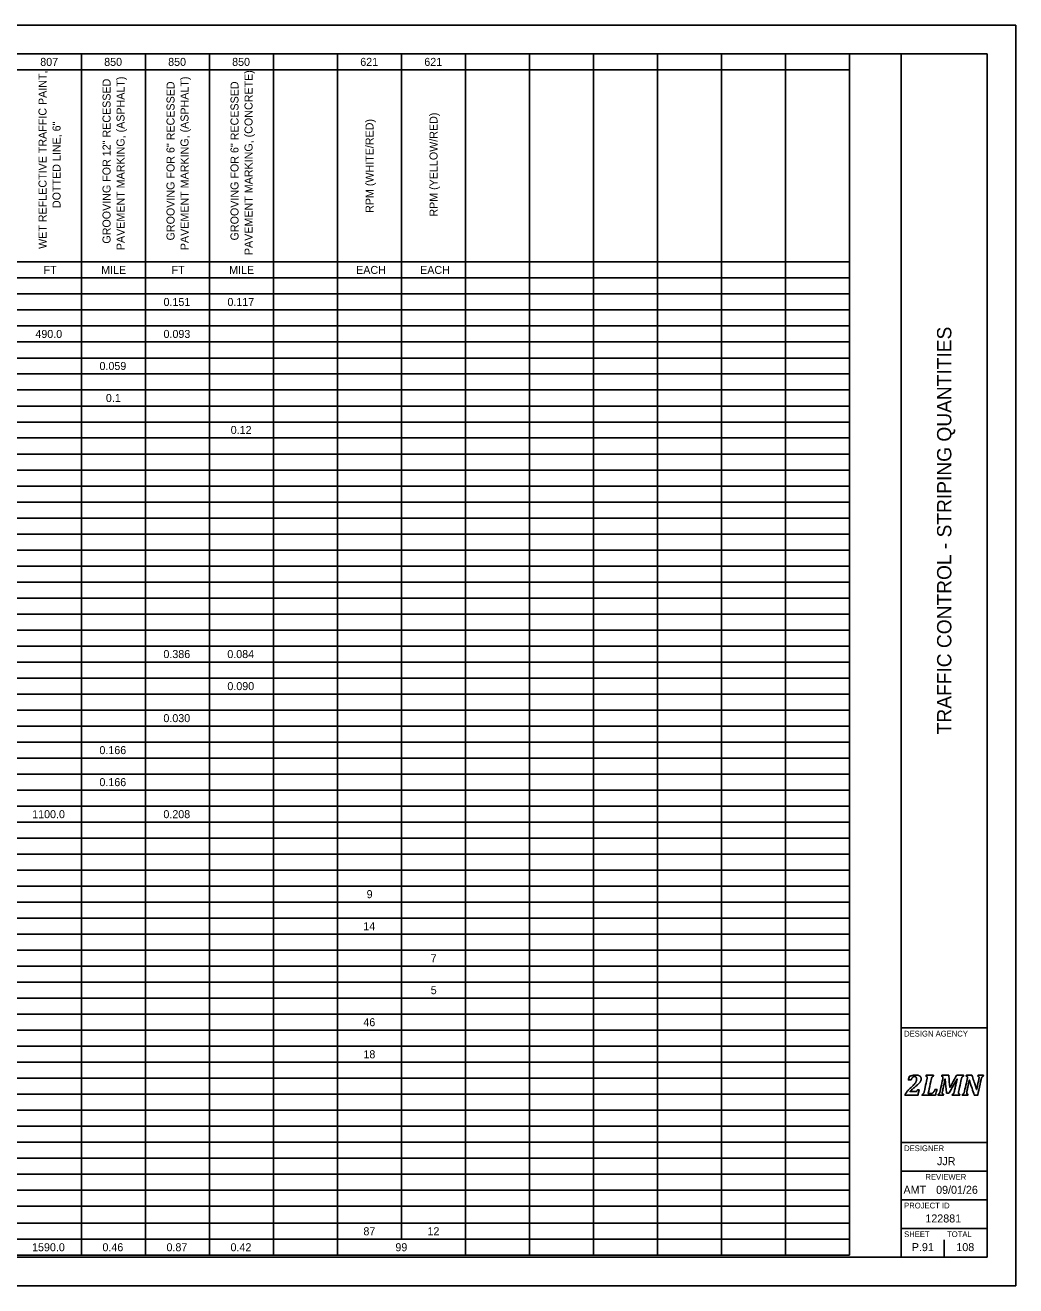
# Model space of a CAD drawing. Extents: x 0 to 34, y 0 to 22.
# Drawn here: x 16.7 to 34, y 0 to 22 of the extents above; entities that cross this region are included whole.
import ezdxf

# ---------------------------------------------------------------- set-up
doc = ezdxf.new("R2010")
doc.units = 0
for name, color, linetype in [('SH_Border', 7, 'Continuous'), ('SH_Cut_Line', 7, 'Continuous'), ('SH_Data', 7, 'Continuous'), ('SH_Text', 7, 'Continuous')]:
    doc.layers.add(name, color=color, linetype=linetype)

msp = doc.modelspace()

# ---------------------------------------------------------------- linework, layer by layer
at = {"layer": 'SH_Border'}
for p, q in [((32, 0.5), (32, 21.5)), ((32, 4.5), (33.5, 4.5)), ((32, 2.5), (33.5, 2.5)), ((32, 2), (33.5, 2)), ((32, 1.5), (33.5, 1.5)), ((32, 1), (33.5, 1))]:
    msp.add_line(p, q, dxfattribs=at)
msp.add_lwpolyline([(1.5, 21.5), (33.5, 21.5), (33.5, 0.5), (1.5, 0.5)], close=True, dxfattribs=at)
at = {"layer": 'SH_Cut_Line'}
msp.add_lwpolyline([(0, 0), (34, 0), (34, 22), (0, 22)], close=True, dxfattribs=at)
at = {"layer": 'SH_Data'}
for p, q in [((32.75, 3.5), (32.75, 3.5)), ((32.375, 0.675), (32.375, 0.675)), ((32.75, 0.5), (32.75, 0.8))]:
    msp.add_line(p, q, dxfattribs=at)
for points in [[(32.237, 3.388), (32.246, 3.388), (32.253, 3.389), (32.258, 3.39), (32.263, 3.392), (32.267, 3.394), (32.27, 3.397), (32.273, 3.401), (32.277, 3.408), (32.281, 3.417), (32.281, 3.417), (32.312, 3.417), (32.312, 3.417), (32.312, 3.417), (32.29, 3.326), (32.29, 3.326), (32.29, 3.326), (32.066, 3.326), (32.066, 3.326), (32.066, 3.326), (32.069, 3.343), (32.069, 3.343), (32.078, 3.358), (32.091, 3.375), (32.106, 3.394), (32.122, 3.412), (32.144, 3.435), (32.172, 3.462), (32.197, 3.486), (32.217, 3.506), (32.23, 3.521), (32.243, 3.537), (32.253, 3.551), (32.259, 3.566), (32.266, 3.58), (32.269, 3.595), (32.269, 3.61), (32.269, 3.622), (32.266, 3.632), (32.26, 3.64), (32.253, 3.647), (32.245, 3.65), (32.234, 3.65), (32.22, 3.65), (32.208, 3.646), (32.198, 3.636), (32.188, 3.627), (32.18, 3.613), (32.172, 3.593), (32.172, 3.593), (32.126, 3.593), (32.126, 3.593), (32.126, 3.593), (32.14, 3.654), (32.14, 3.654), (32.166, 3.663), (32.188, 3.669), (32.205, 3.673), (32.223, 3.676), (32.24, 3.678), (32.258, 3.678), (32.278, 3.678), (32.295, 3.675), (32.309, 3.669), (32.322, 3.664), (32.332, 3.656), (32.339, 3.646), (32.345, 3.637), (32.348, 3.626), (32.348, 3.613), (32.348, 3.602), (32.346, 3.591), (32.342, 3.581), (32.339, 3.571), (32.333, 3.56), (32.324, 3.549), (32.315, 3.539), (32.304, 3.526), (32.289, 3.513), (32.275, 3.499), (32.254, 3.482), (32.228, 3.46), (32.216, 3.45), (32.202, 3.438), (32.188, 3.425), (32.174, 3.412), (32.162, 3.4), (32.154, 3.391), (32.154, 3.391), (32.153, 3.388), (32.153, 3.388), (32.153, 3.388), (32.237, 3.388), (32.237, 3.388)], [(32.237, 3.388), (32.237, 3.388), (32.153, 3.388), (32.153, 3.388), (32.153, 3.388), (32.154, 3.391), (32.154, 3.391), (32.162, 3.4), (32.174, 3.412), (32.188, 3.425), (32.202, 3.438), (32.216, 3.45), (32.228, 3.46), (32.254, 3.482), (32.275, 3.499), (32.289, 3.513), (32.304, 3.526), (32.315, 3.539), (32.324, 3.549), (32.333, 3.56), (32.339, 3.571), (32.342, 3.581), (32.346, 3.591), (32.348, 3.602), (32.348, 3.613), (32.348, 3.626), (32.345, 3.637), (32.339, 3.646), (32.332, 3.656), (32.322, 3.664), (32.309, 3.669), (32.295, 3.675), (32.278, 3.678), (32.258, 3.678), (32.24, 3.678), (32.223, 3.676), (32.205, 3.673), (32.188, 3.669), (32.166, 3.663), (32.14, 3.654), (32.14, 3.654), (32.126, 3.593), (32.126, 3.593), (32.126, 3.593), (32.172, 3.593), (32.172, 3.593), (32.18, 3.613), (32.188, 3.627), (32.198, 3.636), (32.208, 3.646), (32.22, 3.65), (32.234, 3.65), (32.245, 3.65), (32.253, 3.647), (32.26, 3.64), (32.266, 3.632), (32.269, 3.622), (32.269, 3.61), (32.269, 3.595), (32.266, 3.58), (32.259, 3.566), (32.253, 3.551), (32.243, 3.537), (32.23, 3.521), (32.217, 3.506), (32.197, 3.486), (32.172, 3.462), (32.144, 3.435), (32.122, 3.412), (32.106, 3.394), (32.091, 3.375), (32.078, 3.358), (32.069, 3.343), (32.069, 3.343), (32.066, 3.326), (32.066, 3.326), (32.066, 3.326), (32.29, 3.326), (32.29, 3.326), (32.29, 3.326), (32.312, 3.417), (32.312, 3.417), (32.312, 3.417), (32.281, 3.417), (32.281, 3.417), (32.277, 3.408), (32.273, 3.401), (32.27, 3.397), (32.267, 3.394), (32.263, 3.392), (32.258, 3.39), (32.253, 3.389), (32.246, 3.388), (32.237, 3.388)], [(32.518, 3.356), (32.527, 3.356), (32.533, 3.357), (32.538, 3.358), (32.542, 3.36), (32.546, 3.362), (32.55, 3.365), (32.554, 3.368), (32.558, 3.372), (32.562, 3.377), (32.567, 3.382), (32.571, 3.388), (32.576, 3.397), (32.58, 3.405), (32.585, 3.415), (32.589, 3.427), (32.589, 3.427), (32.624, 3.427), (32.624, 3.427), (32.624, 3.427), (32.598, 3.326), (32.598, 3.326), (32.598, 3.326), (32.365, 3.326), (32.365, 3.326), (32.365, 3.326), (32.369, 3.343), (32.369, 3.343), (32.376, 3.345), (32.381, 3.348), (32.385, 3.351), (32.389, 3.355), (32.392, 3.36), (32.395, 3.366), (32.398, 3.373), (32.4, 3.382), (32.403, 3.395), (32.403, 3.395), (32.449, 3.605), (32.449, 3.605), (32.452, 3.615), (32.453, 3.625), (32.453, 3.635), (32.453, 3.642), (32.451, 3.647), (32.448, 3.651), (32.444, 3.654), (32.439, 3.656), (32.432, 3.657), (32.432, 3.657), (32.435, 3.674), (32.435, 3.674), (32.435, 3.674), (32.563, 3.674), (32.563, 3.674), (32.563, 3.674), (32.559, 3.657), (32.559, 3.657), (32.552, 3.655), (32.547, 3.652), (32.543, 3.649), (32.539, 3.645), (32.536, 3.64), (32.533, 3.634), (32.531, 3.627), (32.528, 3.618), (32.525, 3.605), (32.525, 3.605), (32.47, 3.356), (32.47, 3.356), (32.47, 3.356), (32.518, 3.356), (32.518, 3.356)], [(32.518, 3.356), (32.518, 3.356), (32.47, 3.356), (32.47, 3.356), (32.47, 3.356), (32.525, 3.605), (32.525, 3.605), (32.528, 3.618), (32.531, 3.627), (32.533, 3.634), (32.536, 3.64), (32.539, 3.645), (32.543, 3.649), (32.547, 3.652), (32.552, 3.655), (32.559, 3.657), (32.559, 3.657), (32.563, 3.674), (32.563, 3.674), (32.563, 3.674), (32.435, 3.674), (32.435, 3.674), (32.435, 3.674), (32.432, 3.657), (32.432, 3.657), (32.439, 3.656), (32.444, 3.654), (32.448, 3.651), (32.451, 3.647), (32.453, 3.642), (32.453, 3.635), (32.453, 3.625), (32.452, 3.615), (32.449, 3.605), (32.449, 3.605), (32.403, 3.395), (32.403, 3.395), (32.4, 3.382), (32.398, 3.373), (32.395, 3.366), (32.392, 3.36), (32.389, 3.355), (32.385, 3.351), (32.381, 3.348), (32.376, 3.345), (32.369, 3.343), (32.369, 3.343), (32.365, 3.326), (32.365, 3.326), (32.365, 3.326), (32.598, 3.326), (32.598, 3.326), (32.598, 3.326), (32.624, 3.427), (32.624, 3.427), (32.624, 3.427), (32.589, 3.427), (32.589, 3.427), (32.585, 3.415), (32.58, 3.405), (32.576, 3.397), (32.571, 3.388), (32.567, 3.382), (32.562, 3.377), (32.558, 3.372), (32.554, 3.368), (32.55, 3.365), (32.546, 3.362), (32.542, 3.36), (32.538, 3.358), (32.533, 3.357), (32.527, 3.356), (32.518, 3.356)], [(32.829, 3.674), (32.829, 3.674), (32.849, 3.461), (32.849, 3.461), (32.849, 3.461), (32.969, 3.674), (32.969, 3.674), (32.969, 3.674), (33.087, 3.674), (33.087, 3.674), (33.087, 3.674), (33.084, 3.657), (33.084, 3.657), (33.077, 3.655), (33.071, 3.652), (33.067, 3.649), (33.064, 3.645), (33.06, 3.64), (33.058, 3.634), (33.055, 3.627), (33.052, 3.618), (33.05, 3.605), (33.05, 3.605), (33.003, 3.395), (33.003, 3.395), (33.002, 3.39), (33.002, 3.387), (33.001, 3.384), (33.001, 3.382), (33.001, 3.379), (33, 3.376), (33, 3.373), (33, 3.369), (33, 3.365), (33, 3.358), (33.002, 3.353), (33.005, 3.349), (33.008, 3.346), (33.014, 3.344), (33.021, 3.343), (33.021, 3.343), (33.018, 3.326), (33.018, 3.326), (33.018, 3.326), (32.89, 3.326), (32.89, 3.326), (32.89, 3.326), (32.893, 3.343), (32.893, 3.343), (32.9, 3.345), (32.906, 3.348), (32.91, 3.351), (32.914, 3.355), (32.917, 3.36), (32.919, 3.366), (32.922, 3.373), (32.925, 3.382), (32.928, 3.395), (32.928, 3.395), (32.951, 3.502), (32.951, 3.502), (32.954, 3.513), (32.957, 3.529), (32.962, 3.548), (32.967, 3.568), (32.972, 3.588), (32.978, 3.609), (32.978, 3.609), (32.973, 3.609), (32.973, 3.609), (32.965, 3.594), (32.957, 3.579), (32.948, 3.563), (32.948, 3.563), (32.833, 3.364), (32.833, 3.364), (32.833, 3.364), (32.792, 3.364), (32.792, 3.364), (32.792, 3.364), (32.775, 3.518), (32.775, 3.518), (32.773, 3.537), (32.772, 3.554), (32.77, 3.569), (32.769, 3.583), (32.768, 3.597), (32.768, 3.611), (32.768, 3.611), (32.764, 3.611), (32.764, 3.611), (32.761, 3.596), (32.758, 3.578), (32.755, 3.558), (32.751, 3.538), (32.747, 3.521), (32.744, 3.507), (32.744, 3.507), (32.72, 3.395), (32.72, 3.395), (32.719, 3.39), (32.718, 3.387), (32.718, 3.384), (32.717, 3.382), (32.717, 3.379), (32.717, 3.376), (32.717, 3.373), (32.716, 3.369), (32.716, 3.365), (32.716, 3.358), (32.718, 3.353), (32.721, 3.349), (32.725, 3.346), (32.73, 3.344), (32.738, 3.343), (32.738, 3.343), (32.734, 3.326), (32.734, 3.326), (32.734, 3.326), (32.641, 3.326), (32.641, 3.326), (32.641, 3.326), (32.644, 3.343), (32.644, 3.343), (32.651, 3.345), (32.657, 3.348), (32.661, 3.351), (32.665, 3.355), (32.668, 3.36), (32.67, 3.366), (32.673, 3.373), (32.676, 3.382), (32.679, 3.395), (32.679, 3.395), (32.725, 3.605), (32.725, 3.605), (32.727, 3.615), (32.728, 3.625), (32.728, 3.635), (32.728, 3.642), (32.727, 3.647), (32.723, 3.651), (32.72, 3.654), (32.715, 3.656), (32.707, 3.657), (32.707, 3.657), (32.711, 3.674), (32.711, 3.674), (32.711, 3.674), (32.829, 3.674), (32.829, 3.674)], [(32.829, 3.674), (32.829, 3.674), (32.711, 3.674), (32.711, 3.674), (32.711, 3.674), (32.707, 3.657), (32.707, 3.657), (32.715, 3.656), (32.72, 3.654), (32.723, 3.651), (32.727, 3.647), (32.728, 3.642), (32.728, 3.635), (32.728, 3.625), (32.727, 3.615), (32.725, 3.605), (32.725, 3.605), (32.679, 3.395), (32.679, 3.395), (32.676, 3.382), (32.673, 3.373), (32.67, 3.366), (32.668, 3.36), (32.665, 3.355), (32.661, 3.351), (32.657, 3.348), (32.651, 3.345), (32.644, 3.343), (32.644, 3.343), (32.641, 3.326), (32.641, 3.326), (32.641, 3.326), (32.734, 3.326), (32.734, 3.326), (32.734, 3.326), (32.738, 3.343), (32.738, 3.343), (32.73, 3.344), (32.725, 3.346), (32.721, 3.349), (32.718, 3.353), (32.716, 3.358), (32.716, 3.365), (32.716, 3.369), (32.717, 3.373), (32.717, 3.376), (32.717, 3.379), (32.717, 3.382), (32.718, 3.384), (32.718, 3.387), (32.719, 3.39), (32.72, 3.395), (32.72, 3.395), (32.744, 3.507), (32.744, 3.507), (32.747, 3.521), (32.751, 3.538), (32.755, 3.558), (32.758, 3.578), (32.761, 3.596), (32.764, 3.611), (32.764, 3.611), (32.768, 3.611), (32.768, 3.611), (32.768, 3.597), (32.769, 3.583), (32.77, 3.569), (32.772, 3.554), (32.773, 3.537), (32.775, 3.518), (32.775, 3.518), (32.792, 3.364), (32.792, 3.364), (32.792, 3.364), (32.833, 3.364), (32.833, 3.364), (32.833, 3.364), (32.948, 3.563), (32.948, 3.563), (32.957, 3.579), (32.965, 3.594), (32.973, 3.609), (32.973, 3.609), (32.978, 3.609), (32.978, 3.609), (32.972, 3.588), (32.967, 3.568), (32.962, 3.548), (32.957, 3.529), (32.954, 3.513), (32.951, 3.502), (32.951, 3.502), (32.928, 3.395), (32.928, 3.395), (32.925, 3.382), (32.922, 3.373), (32.919, 3.366), (32.917, 3.36), (32.914, 3.355), (32.91, 3.351), (32.906, 3.348), (32.9, 3.345), (32.893, 3.343), (32.893, 3.343), (32.89, 3.326), (32.89, 3.326), (32.89, 3.326), (33.018, 3.326), (33.018, 3.326), (33.018, 3.326), (33.021, 3.343), (33.021, 3.343), (33.014, 3.344), (33.008, 3.346), (33.005, 3.349), (33.002, 3.353), (33, 3.358), (33, 3.365), (33, 3.369), (33, 3.373), (33, 3.376), (33.001, 3.379), (33.001, 3.382), (33.001, 3.384), (33.002, 3.387), (33.002, 3.39), (33.003, 3.395), (33.003, 3.395), (33.05, 3.605), (33.05, 3.605), (33.052, 3.618), (33.055, 3.627), (33.058, 3.634), (33.06, 3.64), (33.064, 3.645), (33.067, 3.649), (33.071, 3.652), (33.077, 3.655), (33.084, 3.657), (33.084, 3.657), (33.087, 3.674), (33.087, 3.674), (33.087, 3.674), (32.969, 3.674), (32.969, 3.674), (32.969, 3.674), (32.849, 3.461), (32.849, 3.461), (32.849, 3.461), (32.829, 3.674), (32.829, 3.674)], [(33.137, 3.674), (33.137, 3.674), (33.234, 3.674), (33.234, 3.674), (33.234, 3.674), (33.283, 3.53), (33.283, 3.53), (33.296, 3.49), (33.307, 3.456), (33.315, 3.426), (33.315, 3.426), (33.318, 3.426), (33.318, 3.426), (33.323, 3.455), (33.329, 3.488), (33.337, 3.523), (33.337, 3.523), (33.355, 3.605), (33.355, 3.605), (33.357, 3.615), (33.358, 3.625), (33.358, 3.635), (33.358, 3.642), (33.357, 3.647), (33.353, 3.651), (33.35, 3.654), (33.345, 3.656), (33.337, 3.657), (33.337, 3.657), (33.341, 3.674), (33.341, 3.674), (33.341, 3.674), (33.434, 3.674), (33.434, 3.674), (33.434, 3.674), (33.431, 3.657), (33.431, 3.657), (33.424, 3.655), (33.418, 3.652), (33.414, 3.649), (33.41, 3.645), (33.407, 3.64), (33.405, 3.634), (33.402, 3.627), (33.399, 3.618), (33.396, 3.605), (33.396, 3.605), (33.335, 3.326), (33.335, 3.326), (33.335, 3.326), (33.277, 3.326), (33.277, 3.326), (33.277, 3.326), (33.216, 3.504), (33.216, 3.504), (33.211, 3.518), (33.207, 3.531), (33.204, 3.543), (33.2, 3.556), (33.195, 3.571), (33.19, 3.59), (33.19, 3.59), (33.186, 3.59), (33.186, 3.59), (33.185, 3.579), (33.182, 3.563), (33.179, 3.543), (33.175, 3.523), (33.17, 3.501), (33.165, 3.478), (33.165, 3.478), (33.147, 3.395), (33.147, 3.395), (33.146, 3.39), (33.145, 3.387), (33.145, 3.384), (33.144, 3.382), (33.144, 3.379), (33.144, 3.376), (33.143, 3.373), (33.143, 3.369), (33.143, 3.365), (33.143, 3.358), (33.145, 3.353), (33.148, 3.349), (33.152, 3.346), (33.157, 3.344), (33.164, 3.343), (33.164, 3.343), (33.161, 3.326), (33.161, 3.326), (33.161, 3.326), (33.067, 3.326), (33.067, 3.326), (33.067, 3.326), (33.071, 3.343), (33.071, 3.343), (33.078, 3.345), (33.083, 3.348), (33.087, 3.351), (33.091, 3.355), (33.094, 3.36), (33.097, 3.366), (33.1, 3.373), (33.102, 3.382), (33.105, 3.395), (33.105, 3.395), (33.151, 3.605), (33.151, 3.605), (33.154, 3.615), (33.155, 3.625), (33.155, 3.635), (33.155, 3.642), (33.153, 3.647), (33.15, 3.651), (33.146, 3.654), (33.141, 3.656), (33.134, 3.657), (33.134, 3.657), (33.137, 3.674), (33.137, 3.674)], [(33.137, 3.674), (33.137, 3.674), (33.134, 3.657), (33.134, 3.657), (33.141, 3.656), (33.146, 3.654), (33.15, 3.651), (33.153, 3.647), (33.155, 3.642), (33.155, 3.635), (33.155, 3.625), (33.154, 3.615), (33.151, 3.605), (33.151, 3.605), (33.105, 3.395), (33.105, 3.395), (33.102, 3.382), (33.1, 3.373), (33.097, 3.366), (33.094, 3.36), (33.091, 3.355), (33.087, 3.351), (33.083, 3.348), (33.078, 3.345), (33.071, 3.343), (33.071, 3.343), (33.067, 3.326), (33.067, 3.326), (33.067, 3.326), (33.161, 3.326), (33.161, 3.326), (33.161, 3.326), (33.164, 3.343), (33.164, 3.343), (33.157, 3.344), (33.152, 3.346), (33.148, 3.349), (33.145, 3.353), (33.143, 3.358), (33.143, 3.365), (33.143, 3.369), (33.143, 3.373), (33.144, 3.376), (33.144, 3.379), (33.144, 3.382), (33.145, 3.384), (33.145, 3.387), (33.146, 3.39), (33.147, 3.395), (33.147, 3.395), (33.165, 3.478), (33.165, 3.478), (33.17, 3.501), (33.175, 3.523), (33.179, 3.543), (33.182, 3.563), (33.185, 3.579), (33.186, 3.59), (33.186, 3.59), (33.19, 3.59), (33.19, 3.59), (33.195, 3.571), (33.2, 3.556), (33.204, 3.543), (33.207, 3.531), (33.211, 3.518), (33.216, 3.504), (33.216, 3.504), (33.277, 3.326), (33.277, 3.326), (33.277, 3.326), (33.335, 3.326), (33.335, 3.326), (33.335, 3.326), (33.396, 3.605), (33.396, 3.605), (33.399, 3.618), (33.402, 3.627), (33.405, 3.634), (33.407, 3.64), (33.41, 3.645), (33.414, 3.649), (33.418, 3.652), (33.424, 3.655), (33.431, 3.657), (33.431, 3.657), (33.434, 3.674), (33.434, 3.674), (33.434, 3.674), (33.341, 3.674), (33.341, 3.674), (33.341, 3.674), (33.337, 3.657), (33.337, 3.657), (33.345, 3.656), (33.35, 3.654), (33.353, 3.651), (33.357, 3.647), (33.358, 3.642), (33.358, 3.635), (33.358, 3.625), (33.357, 3.615), (33.355, 3.605), (33.355, 3.605), (33.337, 3.523), (33.337, 3.523), (33.329, 3.488), (33.323, 3.455), (33.318, 3.426), (33.318, 3.426), (33.315, 3.426), (33.315, 3.426), (33.307, 3.456), (33.296, 3.49), (33.283, 3.53), (33.283, 3.53), (33.234, 3.674), (33.234, 3.674), (33.234, 3.674), (33.137, 3.674), (33.137, 3.674)]]:
    msp.add_open_spline(points, degree=3, dxfattribs=at)
at = {"layer": 'SH_Text'}
for p, q in [((1.536, 21.5), (31.097, 21.5)), ((17.688, 21.5), (17.688, 0.533)), ((18.806, 21.5), (18.806, 0.533)), ((19.923, 21.5), (19.923, 0.533)), ((21.041, 21.5), (21.041, 0.533)), ((22.158, 21.5), (22.158, 0.533)), ((23.275, 21.5), (23.275, 0.812)), ((24.393, 21.5), (24.393, 0.533)), ((25.51, 21.5), (25.51, 0.533)), ((26.627, 21.5), (26.627, 0.533)), ((27.745, 21.5), (27.745, 0.533)), ((28.862, 21.5), (28.862, 0.533)), ((29.979, 21.5), (29.979, 0.533)), ((31.097, 21.5), (31.097, 0.533)), ((8.749, 21.221), (31.097, 21.221)), ((8.749, 17.869), (31.097, 17.869)), ((1.536, 17.589), (31.097, 17.589)), ((1.536, 17.31), (31.097, 17.31)), ((1.536, 17.031), (31.097, 17.031)), ((1.536, 16.751), (31.097, 16.751)), ((1.536, 16.472), (31.097, 16.472)), ((1.536, 16.192), (31.097, 16.192)), ((1.536, 15.913), (31.097, 15.913)), ((1.536, 15.634), (31.097, 15.634)), ((1.536, 15.354), (31.097, 15.354)), ((1.536, 15.075), (31.097, 15.075)), ((1.536, 14.796), (31.097, 14.796)), ((1.536, 14.516), (31.097, 14.516)), ((1.536, 14.237), (31.097, 14.237)), ((1.536, 13.958), (31.097, 13.958)), ((1.536, 13.678), (31.097, 13.678)), ((1.536, 13.399), (31.097, 13.399)), ((1.536, 13.12), (31.097, 13.12)), ((1.536, 12.84), (31.097, 12.84)), ((1.536, 12.561), (31.097, 12.561)), ((1.536, 12.282), (31.097, 12.282)), ((1.536, 12.002), (31.097, 12.002)), ((1.536, 11.723), (31.097, 11.723)), ((1.536, 11.444), (31.097, 11.444)), ((1.536, 11.164), (31.097, 11.164)), ((1.536, 10.885), (31.097, 10.885)), ((1.536, 10.606), (31.097, 10.606)), ((1.536, 10.326), (31.097, 10.326)), ((1.536, 10.047), (31.097, 10.047)), ((1.536, 9.768), (31.097, 9.768)), ((1.536, 9.488), (31.097, 9.488)), ((1.536, 9.209), (31.097, 9.209)), ((1.536, 8.93), (31.097, 8.93)), ((1.536, 8.65), (31.097, 8.65)), ((1.536, 8.371), (31.097, 8.371)), ((1.536, 8.092), (31.097, 8.092)), ((1.536, 7.812), (31.097, 7.812)), ((1.536, 7.533), (31.097, 7.533)), ((1.536, 7.254), (31.097, 7.254)), ((1.536, 6.974), (31.097, 6.974)), ((1.536, 6.695), (31.097, 6.695)), ((1.536, 6.415), (31.097, 6.415)), ((1.536, 6.136), (31.097, 6.136)), ((1.536, 5.857), (31.097, 5.857)), ((1.536, 5.577), (31.097, 5.577)), ((1.536, 5.298), (31.097, 5.298)), ((1.536, 5.019), (31.097, 5.019)), ((1.536, 4.739), (31.097, 4.739)), ((1.536, 4.46), (31.097, 4.46)), ((1.536, 4.181), (31.097, 4.181)), ((1.536, 3.901), (31.097, 3.901)), ((1.536, 3.622), (31.097, 3.622)), ((1.536, 3.343), (31.097, 3.343)), ((1.536, 3.063), (31.097, 3.063)), ((1.536, 2.784), (31.097, 2.784)), ((1.536, 2.505), (31.097, 2.505)), ((1.536, 2.225), (31.097, 2.225)), ((1.536, 1.946), (31.097, 1.946)), ((1.536, 1.667), (31.097, 1.667)), ((1.536, 1.387), (31.097, 1.387)), ((1.536, 1.092), (22.158, 1.092)), ((22.158, 1.092), (24.393, 1.092)), ((24.393, 1.092), (31.097, 1.092)), ((1.536, 0.812), (31.097, 0.812)), ((1.536, 0.533), (31.097, 0.533))]:
    msp.add_line(p, q, dxfattribs=at)

# ---------------------------------------------------------------- texts
at = {"layer": 'SH_Data'}
msp.add_text('TRAFFIC CONTROL - STRIPING QUANTITIES', height=0.25, rotation=90, dxfattribs=at).set_placement((32.875, 9.625))
for s, height, p in [('DESIGN AGENCY', 0.1, (32.05, 4.35)), ('DESIGNER', 0.1, (32.05, 2.35)), ('JJR', 0.14, (32.624, 2.105)), ('REVIEWER', 0.1, (32.422, 1.85)), ('AMT', 0.14, (32.039, 1.605)), ('09/01/26', 0.14, (32.609, 1.605)), ('PROJECT ID', 0.1, (32.05, 1.35)), ('122881', 0.14, (32.421, 1.105)), ('SHEET', 0.1, (32.05, 0.85)), ('TOTAL', 0.1, (32.8, 0.85)), ('P.91', 0.14, (32.184, 0.605)), ('108', 0.14, (32.962, 0.605))]:
    msp.add_text(s, height=height, dxfattribs=at).set_placement(p)
at = {"layer": 'SH_Text'}
for s, height, p in [('807', 0.1397, (16.968, 21.29)), ('850', 0.1397, (18.084, 21.29)), ('850', 0.1397, (19.201, 21.29)), ('850', 0.1397, (20.318, 21.29)), ('621', 0.1397, (22.555, 21.29)), ('621', 0.1397, (23.673, 21.29)), ('FT', 0.1397, (17.026, 17.659)), ('MILE', 0.1397, (18.031, 17.659)), ('FT', 0.1397, (19.261, 17.659)), ('MILE', 0.1397, (20.266, 17.659)), ('EACH', 0.1397, (22.483, 17.659)), ('EACH', 0.1397, (23.6, 17.659)), ('0.151', 0.1397, (19.12, 17.1)), ('0.117', 0.1397, (20.236, 17.1)), ('490.0', 0.1397, (16.883, 16.542)), ('0.093', 0.1397, (19.12, 16.542)), ('0.059', 0.1397, (18.002, 15.983)), ('0.1', 0.1397, (18.114, 15.424)), ('0.12', 0.1397, (20.293, 14.866)), ('0.386', 0.1397, (19.118, 10.955)), ('0.084', 0.1397, (20.234, 10.955)), ('0.090', 0.1397, (20.235, 10.396)), ('0.030', 0.1397, (19.118, 9.837)), ('0.166', 0.1397, (18.001, 9.279)), ('0.166', 0.1397, (18.001, 8.72)), ('1100.0', 0.1397, (16.827, 8.161)), ('0.208', 0.1397, (19.118, 8.161)), ('9', 0.14, (22.666, 6.765)), ('14', 0.1397, (22.608, 6.206)), ('7', 0.14, (23.783, 5.647)), ('5', 0.14, (23.785, 5.089)), ('46', 0.1397, (22.609, 4.53)), ('18', 0.1397, (22.61, 3.971)), ('87', 0.1397, (22.61, 0.882)), ('12', 0.1397, (23.729, 0.882)), ('1590.0', 0.1397, (16.825, 0.603)), ('0.46', 0.1397, (18.054, 0.603)), ('0.87', 0.1397, (19.172, 0.603)), ('0.42', 0.1397, (20.29, 0.603)), ('99', 0.1397, (23.168, 0.603))]:
    msp.add_text(s, height=height, dxfattribs=at).set_placement(p)
for s, p in [('WET REFLECTIVE TRAFFIC PAINT, ', (17.077, 18.096)), ('PAVEMENT MARKING, (CONCRETE)', (20.674, 17.988)), ('GROOVING FOR 12" RECESSED ', (18.195, 18.188)), ('PAVEMENT MARKING, (ASPHALT)', (18.439, 18.074)), ('GROOVING FOR 6" RECESSED ', (19.312, 18.244)), ('PAVEMENT MARKING, (ASPHALT)', (19.556, 18.074)), ('GROOVING FOR 6" RECESSED ', (20.429, 18.244)), ('RPM (YELLOW/RED)', (23.904, 18.659)), ('DOTTED LINE, 6"', (17.322, 18.809)), ('RPM (WHITE/RED)', (22.786, 18.724))]:
    msp.add_text(s, height=0.13967, rotation=90, dxfattribs=at).set_placement(p)

doc.saveas('drawing.dxf')
